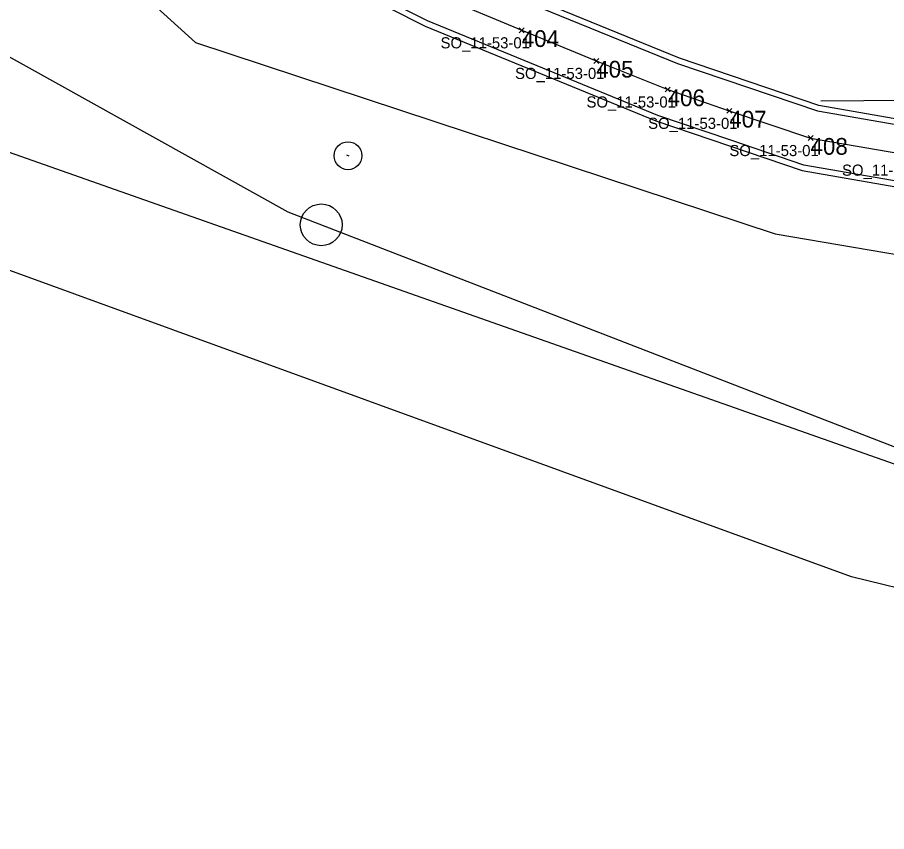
# Model space of a CAD drawing. Extents: x -728800 to -728100, y -1073200 to -1072700.
# Drawn here: x -728571.08 to -728539.85, y -1073048.37 to -1073019.12 of the extents above; entities that cross this region are included whole.
import ezdxf

# ---------------------------------------------------------------- set-up
doc = ezdxf.new("R2010")
doc.units = 0
for name, color, linetype in [('A1_OBVOD Spravy železnic', 7, 'Continuous'), ('A2_OBVOD STAVBY', 7, 'Continuous'), ('B1_body_poloha', 7, 'Continuous'), ('B2_body_číslo', 7, 'Continuous'), ('B3_body_popiska', 7, 'Continuous'), ('B4_Bodové pole', 7, 'Continuous'), ('B6_JŽM', 7, 'Continuous'), ('KOS_kabelová trasa VO', 7, 'Continuous'), ('ZA_02_Dočasný_do_1_roku', 7, 'Continuous')]:
    doc.layers.add(name, color=color, linetype=linetype)

msp = doc.modelspace()

# ---------------------------------------------------------------- linework, layer by layer
at = {"layer": 'A1_OBVOD Spravy železnic'}
msp.add_lwpolyline([(-728582.13, -1073004.22), (-728564.68, -1073020.02), (-728543.86, -1073026.9), (-728510.71, -1073032.54), (-728510.22, -1073036.28), (-728509.415, -1073042.185), (-728509.9, -1073046.86), (-728541.12, -1073039.22), (-728572.55, -1073027.78)], dxfattribs=at)
at = {"layer": 'A2_OBVOD STAVBY'}
for points in [[(-728564.164, -1073015.523), (-728556.425, -1073019.431), (-728548.14, -1073022.833), (-728542.882, -1073024.621), (-728538.694, -1073025.349), (-728534.14, -1073025.737), (-728532.664, -1073025.787), (-728522.232, -1073025.806), (-728521.488, -1073028.32), (-728521.545, -1073030.726), (-728521.594, -1073032.788), (-728517.755, -1073032.879), (-728517.209, -1073045.129)], [(-728509.455, -1073035.234), (-728510.689, -1073028.502), (-728511.933, -1073022.707), (-728511.986, -1073020.002), (-728513.157, -1073020.217), (-728515.255, -1073019.379), (-728517.216, -1073018.59), (-728517.096, -1073019.442), (-728517.727, -1073020.685), (-728519.2, -1073021.56), (-728519.78, -1073021.597), (-728522.531, -1073023.408), (-728531.159, -1073023.437), (-728533.997, -1073023.341), (-728538.386, -1073022.967), (-728542.291, -1073022.287), (-728547.296, -1073020.586), (-728553.966, -1073017.86)]]:
    msp.add_lwpolyline(points, dxfattribs=at)
at = {"layer": 'B1_body_poloha'}
for p, q in [((-728553.048, -1073019.496), (-728552.872, -1073019.672)), ((-728553.048, -1073019.672), (-728552.872, -1073019.496)), ((-728550.372, -1073020.595), (-728550.196, -1073020.772)), ((-728550.372, -1073020.772), (-728550.196, -1073020.595)), ((-728547.806, -1073021.622), (-728547.63, -1073021.798)), ((-728547.806, -1073021.798), (-728547.63, -1073021.622)), ((-728545.593, -1073022.389), (-728545.416, -1073022.566)), ((-728545.593, -1073022.566), (-728545.416, -1073022.389)), ((-728542.675, -1073023.366), (-728542.498, -1073023.542)), ((-728542.675, -1073023.542), (-728542.498, -1073023.366))]:
    msp.add_line(p, q, dxfattribs=at)
at = {"layer": 'B2_body_číslo'}
for p, q in [((-728552.96, -1073019.584), (-728552.96, -1073019.584)), ((-728550.284, -1073020.683), (-728550.284, -1073020.683)), ((-728547.718, -1073021.71), (-728547.718, -1073021.71)), ((-728545.504, -1073022.477), (-728545.504, -1073022.477)), ((-728542.587, -1073023.454), (-728542.587, -1073023.454))]:
    msp.add_line(p, q, dxfattribs=at)
at = {"layer": 'B4_Bodové pole'}
msp.add_lwpolyline([(-728665.963, -1072915.444), (-728594.709, -1073015.734), (-728502.086, -1073048.369), (-728347.458, -1073023.537)], dxfattribs=at)
at = {"layer": 'B6_JŽM'}
for p, q in [((-728522.835, -1073021.968), (-728542.221, -1073022.127)), ((-728559.154, -1073024.109), (-728559.248, -1073024.073))]:
    msp.add_line(p, q, dxfattribs=at)
msp.add_lwpolyline([(-728300.809, -1073024.355), (-728320.8, -1073026.914), (-728374.008, -1073033.722), (-728429.095, -1073040.747), (-728461.932, -1073044.273), (-728481.199, -1073044.815), (-728499.353, -1073043.648), (-728506.01, -1073042.737), (-728514.574, -1073041.329), (-728535.848, -1073035.998), (-728561.353, -1073026.113), (-728583.963, -1073013.524), (-728603.757, -1072998.891), (-728619.185, -1072984.418), (-728634.193, -1072966.825), (-728646.078, -1072949.194), (-728656.182, -1072930.072), (-728664.987, -1072910.227), (-728668.627, -1072901.808), (-728681.252, -1072876.016), (-728691.886, -1072859.663)], dxfattribs=at)
for centre, radius in [((-728559.201, -1073024.091), 0.5), ((-728560.163, -1073026.574), 0.75)]:
    msp.add_circle(centre, radius, dxfattribs=at)
at = {"layer": 'KOS_kabelová trasa VO'}
msp.add_lwpolyline([(-728561.457, -1073013.169), (-728562.506, -1073015.027), (-728558.898, -1073016.89), (-728555.929, -1073018.337), (-728552.96, -1073019.584), (-728550.284, -1073020.683), (-728547.718, -1073021.71), (-728545.504, -1073022.477), (-728542.587, -1073023.454), (-728538.54, -1073024.158), (-728535.432, -1073024.48), (-728532.705, -1073024.598), (-728529.651, -1073024.677), (-728525.747, -1073024.604), (-728522.277, -1073024.607), (-728519.905, -1073023.659), (-728515.301, -1073022.774)], dxfattribs=at)
at = {"layer": 'ZA_02_Dočasný_do_1_roku'}
for points in [[(-728538.668, -1073025.15), (-728542.832, -1073024.426), (-728545.451, -1073023.536), (-728548.07, -1073022.646), (-728552.206, -1073020.947), (-728556.342, -1073019.249), (-728563.887, -1073015.439)], [(-728554.047, -1073018.043), (-728547.366, -1073020.773), (-728542.341, -1073022.482), (-728538.412, -1073023.165)]]:
    msp.add_lwpolyline(points, dxfattribs=at)

# ---------------------------------------------------------------- texts
at = {"layer": 'B2_body_číslo'}
for s, p in [('404', (-728552.96, -1073020.184)), ('405', (-728550.284, -1073021.283)), ('406', (-728547.718, -1073022.31)), ('407', (-728545.504, -1073023.077)), ('408', (-728542.587, -1073024.054))]:
    msp.add_text(s, height=0.6, dxfattribs=at).set_placement(p)
at = {"layer": 'B3_body_popiska'}
for p in [(-728555.876, -1073020.234), (-728553.2, -1073021.333), (-728550.634, -1073022.36), (-728548.42, -1073023.127), (-728545.503, -1073024.104), (-728541.456, -1073024.808)]:
    msp.add_text('SO_11-53-01', height=0.4, dxfattribs=at).set_placement(p)

doc.saveas('drawing.dxf')
